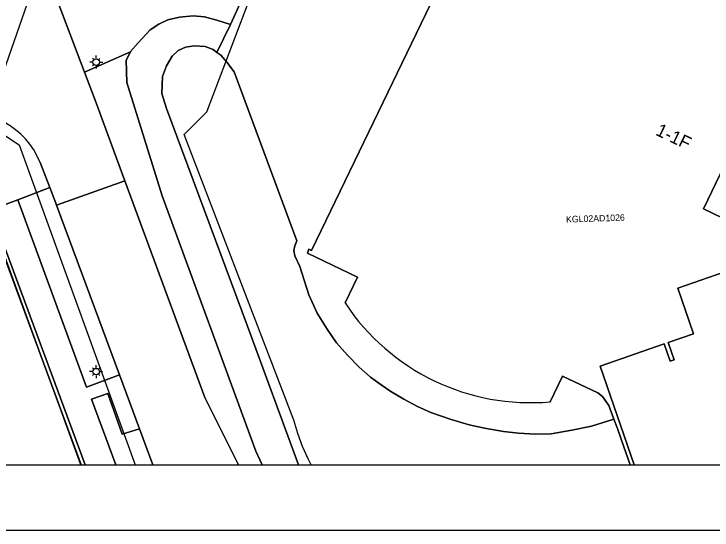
# Model space of a CAD drawing. Extents: x 124901 to 125496, y 515369 to 515789.
# Drawn here: x 125324.5 to 125378, y 515368.5 to 515408.1 of the extents above; entities that cross this region are included whole.
import ezdxf

# ---------------------------------------------------------------- set-up
doc = ezdxf.new("R2010")
doc.units = 0
for name, color, linetype in [('Alg Kaders', 7, 'Continuous'), ('Berm', 7, 'Continuous'), ('Gebouw', 7, 'Continuous'), ('Kunstwerkdeel', 7, 'Continuous'), ('Lichtmast', 7, 'Continuous'), ('Onbegroeid terrein', 7, 'Continuous'), ('Parkeren', 7, 'Continuous'), ('Perceelnummers', 7, 'Continuous'), ('Perceelsgrenzen', 7, 'Continuous'), ('Scheiding', 7, 'Continuous'), ('Teksten', 7, 'Continuous'), ('Vegetatie', 7, 'Continuous'), ('Voetpad', 7, 'Continuous'), ('Water', 7, 'Continuous'), ('Wegen drempel verkeerseiland', 7, 'Continuous'), ('Wegen lokale weg', 7, 'Continuous')]:
    doc.layers.add(name, color=color, linetype=linetype)

msp = doc.modelspace()

# ---------------------------------------------------------------- linework, layer by layer
at = {"layer": 'Alg Kaders'}
for points in [[(125495.925, 515789.043), (124901.425, 515789.043), (124901.425, 515368.543), (125495.925, 515368.543)], [(125490.925, 515784.043), (124906.425, 515784.043), (124906.425, 515373.543), (125490.925, 515373.543)]]:
    msp.add_lwpolyline(points, close=True, dxfattribs=at)
at = {"layer": 'Berm'}
for points in [[(125343.529, 515373.543), (125343.042, 515374.582), (125335.863, 515394.146), (125333.172, 515402.842), (125333.096, 515404.533), (125333.439, 515405.192), (125329.923, 515403.616)], [(125329.923, 515403.616), (125330.728, 515401.491), (125333.01, 515395.297), (125339.124, 515378.7), (125341.704, 515373.543)]]:
    msp.add_lwpolyline(points, dxfattribs=at)
at = {"layer": 'Gebouw'}
for points in [[(125369.39, 515415.78), (125369.201, 515415.396), (125362.079, 515418.876), (125361.86, 515419.52), (125361.55, 515419.41), (125363.598, 515413.583), (125358.714, 515411.866), (125358.33, 515412.96), (125358.02, 515412.85), (125358.42, 515411.7), (125357.93, 515411.45), (125357.51, 515411.13), (125347.289, 515389.969), (125347.1, 515390.06), (125346.99, 515389.77), (125350.825, 515387.907), (125349.87, 515385.94)], [(125372.005, 515373.543), (125369.392, 515381.106), (125374.299, 515382.802), (125374.757, 515381.475), (125375.06, 515381.58), (125374.601, 515382.911), (125376.54, 515383.58), (125375.324, 515387.078), (125380.02, 515388.71), (125380.89, 515391.42), (125377.294, 515393.154), (125380.88, 515400.59), (125380.493, 515400.777), (125384.09, 515408.22), (125376.623, 515411.811), (125376.81, 515412.2), (125374.711, 515413.213), (125369.39, 515415.78)], [(125365.57, 515378.37), (125366.508, 515380.335), (125369.2, 515379.05), (125369.56, 515378.78), (125370.06, 515378.09), (125370.446, 515377.044), (125370.71, 515376.33), (125371.03, 515375.43), (125371.68, 515373.543)]]:
    msp.add_lwpolyline(points, dxfattribs=at)
msp.add_arc((125364.054, 515395.292), 16.99, 213.3987, 275.1178, dxfattribs=at)
at = {"layer": 'Kunstwerkdeel'}
msp.add_lwpolyline([(125329.978, 515421.675), (125320.056, 515393.181)], dxfattribs=at)
at = {"layer": 'Lichtmast'}
for p, q in [((125330.603, 515404.611), (125330.533, 515404.682)), ((125330.815, 515404.699), (125330.815, 515404.899)), ((125331.027, 515404.611), (125331.098, 515404.683)), ((125330.515, 515404.4), (125330.315, 515404.399)), ((125330.603, 515404.187), (125330.531, 515404.116)), ((125330.815, 515404.099), (125330.815, 515403.899)), ((125331.027, 515404.187), (125331.097, 515404.116)), ((125331.115, 515404.399), (125331.315, 515404.399)), ((125330.809, 515380.98), (125330.809, 515381.18)), ((125330.509, 515380.681), (125330.309, 515380.68)), ((125330.597, 515380.892), (125330.527, 515380.963)), ((125331.021, 515380.892), (125331.092, 515380.964)), ((125331.109, 515380.68), (125331.309, 515380.68)), ((125330.597, 515380.468), (125330.525, 515380.397)), ((125330.809, 515380.38), (125330.809, 515380.18)), ((125331.021, 515380.468), (125331.091, 515380.397))]:
    msp.add_line(p, q, dxfattribs=at)
for centre in [(125330.815, 515404.399), (125330.809, 515380.68)]:
    msp.add_circle(centre, 0.25, dxfattribs=at)
at = {"layer": 'Onbegroeid terrein'}
for points in [[(125349.87, 515385.94), (125350.825, 515387.907), (125346.99, 515389.77), (125347.1, 515390.06), (125347.289, 515389.969), (125357.51, 515411.13), (125357.93, 515411.45), (125358.42, 515411.7), (125358.02, 515412.85), (125358.33, 515412.96), (125358.714, 515411.866), (125363.598, 515413.583), (125361.55, 515419.41), (125361.86, 515419.52), (125362.079, 515418.876), (125369.201, 515415.396)], [(125345.594, 515417.203), (125341.107, 515407.269), (125340.052, 515405.141), (125340.345, 515404.931), (125340.817, 515404.394), (125341.382, 515403.642), (125346.181, 515390.69), (125346.021, 515390.324), (125345.952, 515389.972), (125346.028, 515389.558), (125346.393, 515388.741), (125347.098, 515386.561), (125347.739, 515385.155), (125348.485, 515383.922), (125349.22, 515382.892), (125350.052, 515381.951), (125350.933, 515381.032), (125351.801, 515380.257), (125352.638, 515379.657), (125353.377, 515379.161), (125354.371, 515378.563), (125355.414, 515378.016), (125356.437, 515377.553), (125357.993, 515377.02), (125359.355, 515376.61), (125360.527, 515376.361), (125362.004, 515376.104), (125363.134, 515375.975), (125364.429, 515375.898), (125365.648, 515375.917), (125367.213, 515376.19), (125368.737, 515376.493), (125370.446, 515377.044), (125370.06, 515378.09), (125369.56, 515378.78), (125369.2, 515379.05), (125366.508, 515380.335), (125365.57, 515378.37)]]:
    msp.add_lwpolyline(points, dxfattribs=at)
msp.add_arc((125364.054, 515395.292), 16.99, 213.3987, 275.1178, dxfattribs=at)
at = {"layer": 'Parkeren'}
for points in [[(125380.88, 515400.59), (125377.294, 515393.154), (125380.89, 515391.42)], [(125380.02, 515388.71), (125375.324, 515387.078), (125376.54, 515383.58), (125374.601, 515382.911), (125375.06, 515381.58), (125374.757, 515381.475), (125374.299, 515382.802), (125369.392, 515381.106), (125372.005, 515373.543)]]:
    msp.add_lwpolyline(points, dxfattribs=at)
at = {"layer": 'Perceelsgrenzen'}
for points in [[(125329.637, 515373.543), (125321.13, 515396.81), (125308.38, 515404.21), (125310.17, 515407.79), (125313.051, 515410.892), (125315.603, 515413.311), (125318.469, 515416.658), (125321.341, 515419.695), (125324.27, 515423.207), (125326.529, 515425.692), (125328.194, 515427.596), (125330.261, 515431.98), (125312.72, 515440.33), (125296.52, 515406.57), (125290.24, 515409.58), (125288.88, 515406.8), (125279.42, 515411.33)], [(125347.273, 515373.543), (125347.035, 515373.992), (125346.605, 515374.956), (125346.243, 515375.947), (125345.95, 515376.96), (125337.56, 515398.86), (125339.28, 515400.59), (125345.594, 515417.203), (125386.949, 515431.401), (125394.052, 515427.9), (125396.029, 515421.819), (125398.444, 515414.714), (125401.327, 515406.13), (125385.649, 515373.543)], [(125347.273, 515373.543), (125347.035, 515373.992), (125346.605, 515374.956), (125346.243, 515375.947), (125345.95, 515376.96), (125337.56, 515398.86), (125339.28, 515400.59), (125345.594, 515417.203), (125346.053, 515418.41), (125341.448, 515421.165), (125338.281, 515422.912), (125337.767, 515422.004), (125336.439, 515422.819), (125335.946, 515423.097), (125333.303, 515424.585), (125332.521, 515425.055), (125330.281, 515426.402), (125328.194, 515427.596), (125326.529, 515425.692), (125324.27, 515423.207)], [(125329.637, 515373.543), (125321.13, 515396.81), (125308.38, 515404.21), (125310.17, 515407.79), (125324.93, 515398.06), (125333.8, 515373.543)], [(125310.17, 515407.79), (125324.93, 515398.06), (125333.8, 515373.543)]]:
    msp.add_lwpolyline(points, dxfattribs=at)
at = {"layer": 'Scheiding'}
msp.add_line((125342.39, 515384.165), (125346.304, 515373.543), dxfattribs=at)
for points in [[(125337.092, 515405.287), (125336.622, 515404.856)], [(125337.656, 515405.551), (125337.092, 515405.287)], [(125338.324, 515405.65), (125337.656, 515405.551)], [(125339.161, 515405.584), (125338.324, 515405.65)], [(125339.758, 515405.351), (125339.161, 515405.584)], [(125340.052, 515405.141), (125339.758, 515405.351)], [(125336.622, 515404.856), (125336.202, 515404.099)], [(125340.345, 515404.931), (125340.052, 515405.141)], [(125340.817, 515404.394), (125340.345, 515404.931)], [(125336.202, 515404.099), (125335.882, 515403.285)], [(125341.382, 515403.642), (125340.817, 515404.394)], [(125346.181, 515390.69), (125341.382, 515403.642)], [(125335.882, 515403.285), (125335.829, 515401.989)], [(125335.829, 515401.989), (125336.201, 515400.844)], [(125336.201, 515400.844), (125342.39, 515384.165)], [(125329.967, 515373.543), (125322.731, 515393.079), (125322.27, 515394.324), (125309.519, 515389.575), (125309.618, 515389.286), (125309.757, 515389.338), (125313.228, 515390.633), (125322.119, 515393.951), (125329.672, 515373.543)], [(125345.952, 515389.972), (125346.021, 515390.324)], [(125346.021, 515390.324), (125346.181, 515390.69)], [(125346.028, 515389.558), (125345.952, 515389.972)], [(125346.393, 515388.741), (125346.028, 515389.558)], [(125347.098, 515386.561), (125346.393, 515388.741)], [(125347.739, 515385.155), (125347.098, 515386.561)], [(125348.485, 515383.922), (125347.739, 515385.155)], [(125349.22, 515382.892), (125348.485, 515383.922)], [(125350.052, 515381.951), (125349.22, 515382.892)], [(125350.933, 515381.032), (125350.052, 515381.951)], [(125351.801, 515380.257), (125350.933, 515381.032)], [(125352.638, 515379.657), (125351.801, 515380.257)], [(125353.377, 515379.161), (125352.638, 515379.657)], [(125354.371, 515378.563), (125353.377, 515379.161)], [(125355.414, 515378.016), (125354.371, 515378.563)], [(125356.437, 515377.553), (125355.414, 515378.016)], [(125357.993, 515377.02), (125356.437, 515377.553)], [(125359.355, 515376.61), (125357.993, 515377.02)], [(125370.446, 515377.044), (125368.737, 515376.493)], [(125360.527, 515376.361), (125359.355, 515376.61)], [(125362.004, 515376.104), (125360.527, 515376.361)], [(125368.737, 515376.493), (125367.213, 515376.19)], [(125363.134, 515375.975), (125362.004, 515376.104)], [(125364.429, 515375.898), (125363.134, 515375.975)], [(125365.648, 515375.917), (125364.429, 515375.898)], [(125367.213, 515376.19), (125365.648, 515375.917)]]:
    msp.add_lwpolyline(points, dxfattribs=at)
at = {"layer": 'Vegetatie'}
for points in [[(125346.053, 515418.41), (125343.255, 515420.084), (125336.646, 515417.896), (125337.338, 515416.013), (125339.566, 515414.931), (125337.991, 515411.621), (125335.734, 515412.721), (125334.932, 515413.112), (125336.441, 515416.184), (125335.816, 515417.635), (125325.904, 515414.222), (125329.923, 515403.616), (125333.439, 515405.192), (125333.443, 515405.2), (125334.038, 515405.862), (125334.936, 515406.868), (125335.598, 515407.308), (125336.309, 515407.634), (125337.183, 515407.832), (125338.245, 515407.953), (125339.096, 515407.877), (125340.06, 515407.603), (125341.107, 515407.269), (125345.594, 515417.203)], [(125327.274, 515394.777), (125324.804, 515393.847), (125330.07, 515379.488), (125332.598, 515380.436), (125327.785, 515393.438), (125327.728, 515393.593)]]:
    msp.add_lwpolyline(points, close=True, dxfattribs=at)
msp.add_lwpolyline([(125335.149, 515373.543), (125334.13, 515376.296), (125332.801, 515375.881), (125331.715, 515379.002), (125330.467, 515378.562), (125332.324, 515373.543)], dxfattribs=at)
at = {"layer": 'Voetpad'}
for points in [[(125284.824, 515386.545), (125288.363, 515387.728), (125301.396, 515392.085), (125301.516, 515392.111), (125302.293, 515392.278), (125306.463, 515392.734), (125308.363, 515392.942), (125307.872, 515394.367), (125320.73, 515398.796), (125322.27, 515394.324), (125322.731, 515393.079), (125324.804, 515393.847), (125327.274, 515394.777), (125326.532, 515396.708)], [(125332.324, 515373.543), (125330.467, 515378.562), (125331.715, 515379.002), (125332.801, 515375.881), (125334.13, 515376.296), (125332.598, 515380.436), (125330.07, 515379.488), (125324.804, 515393.847), (125322.731, 515393.079), (125329.967, 515373.543)]]:
    msp.add_lwpolyline(points, dxfattribs=at)
msp.add_arc((125320.826, 515394.375), 6.165, 22.2363, 100.538, dxfattribs=at)
at = {"layer": 'Water'}
for points in [[(125346.304, 515373.543), (125342.39, 515384.165), (125336.201, 515400.844), (125335.829, 515401.989), (125335.882, 515403.285), (125336.202, 515404.099), (125336.622, 515404.856), (125337.092, 515405.287), (125337.656, 515405.551), (125338.324, 515405.65), (125339.161, 515405.584), (125339.758, 515405.351), (125340.052, 515405.141), (125341.107, 515407.269), (125340.06, 515407.603), (125339.096, 515407.877), (125338.245, 515407.953), (125337.183, 515407.832), (125336.309, 515407.634), (125335.598, 515407.308), (125334.936, 515406.868), (125334.038, 515405.862), (125333.443, 515405.2), (125333.439, 515405.192), (125333.096, 515404.533), (125333.172, 515402.842), (125335.863, 515394.146), (125343.042, 515374.582), (125343.529, 515373.543)], [(125371.68, 515373.543), (125371.03, 515375.43), (125370.71, 515376.33), (125370.446, 515377.044), (125368.737, 515376.493), (125367.213, 515376.19), (125365.648, 515375.917), (125364.429, 515375.898), (125363.134, 515375.975), (125362.004, 515376.104), (125360.527, 515376.361), (125359.355, 515376.61), (125357.993, 515377.02), (125356.437, 515377.553), (125355.414, 515378.016), (125354.371, 515378.563), (125353.377, 515379.161), (125352.638, 515379.657), (125351.801, 515380.257), (125350.933, 515381.032), (125350.052, 515381.951), (125349.22, 515382.892), (125348.485, 515383.922), (125347.739, 515385.155), (125347.098, 515386.561), (125346.393, 515388.741), (125346.028, 515389.558), (125345.952, 515389.972), (125346.021, 515390.324), (125346.181, 515390.69), (125341.382, 515403.642), (125340.817, 515404.394), (125340.345, 515404.931), (125340.052, 515405.141), (125339.758, 515405.351), (125339.161, 515405.584), (125338.324, 515405.65), (125337.656, 515405.551), (125337.092, 515405.287), (125336.622, 515404.856), (125336.202, 515404.099), (125335.882, 515403.285), (125335.829, 515401.989), (125336.201, 515400.844), (125342.39, 515384.165), (125346.304, 515373.543)], [(125329.672, 515373.543), (125322.119, 515393.951), (125313.228, 515390.633), (125309.757, 515389.338), (125309.618, 515389.286), (125311.263, 515384.426), (125311.857, 515382.696), (125314.952, 515373.543)]]:
    msp.add_lwpolyline(points, dxfattribs=at)
at = {"layer": 'Wegen drempel verkeerseiland'}
for points in [[(125333.01, 515395.297), (125330.728, 515401.491), (125329.923, 515403.616), (125325.904, 515414.222), (125325.195, 515416.155), (125325.106, 515416.399), (125324.235, 515418.867), (125319.117, 515417.06), (125319.92, 515414.8), (125320.031, 515414.443), (125320.732, 515412.187), (125321.272, 515410.449)], [(125326.532, 515396.708), (125327.274, 515394.777), (125327.728, 515393.593), (125327.785, 515393.438), (125333.01, 515395.297)]]:
    msp.add_lwpolyline(points, dxfattribs=at)
msp.add_arc((125320.826, 515394.375), 6.165, 22.2363, 100.538, dxfattribs=at)
at = {"layer": 'Wegen lokale weg'}
msp.add_lwpolyline([(125341.704, 515373.543), (125339.124, 515378.7), (125333.01, 515395.297), (125327.785, 515393.438), (125332.598, 515380.436), (125334.13, 515376.296), (125335.149, 515373.543)], dxfattribs=at)

# ---------------------------------------------------------------- texts
at = {"layer": 'Perceelnummers'}
msp.add_text('KGL02AD1026', height=0.5, rotation=1.8323, dxfattribs=at).set_placement((125366.786, 515392.102))
at = {"layer": 'Teksten'}
msp.add_text('1-1F', height=1, rotation=334.3, dxfattribs=at).set_placement((125373.564, 515398.847))

doc.saveas('drawing.dxf')
